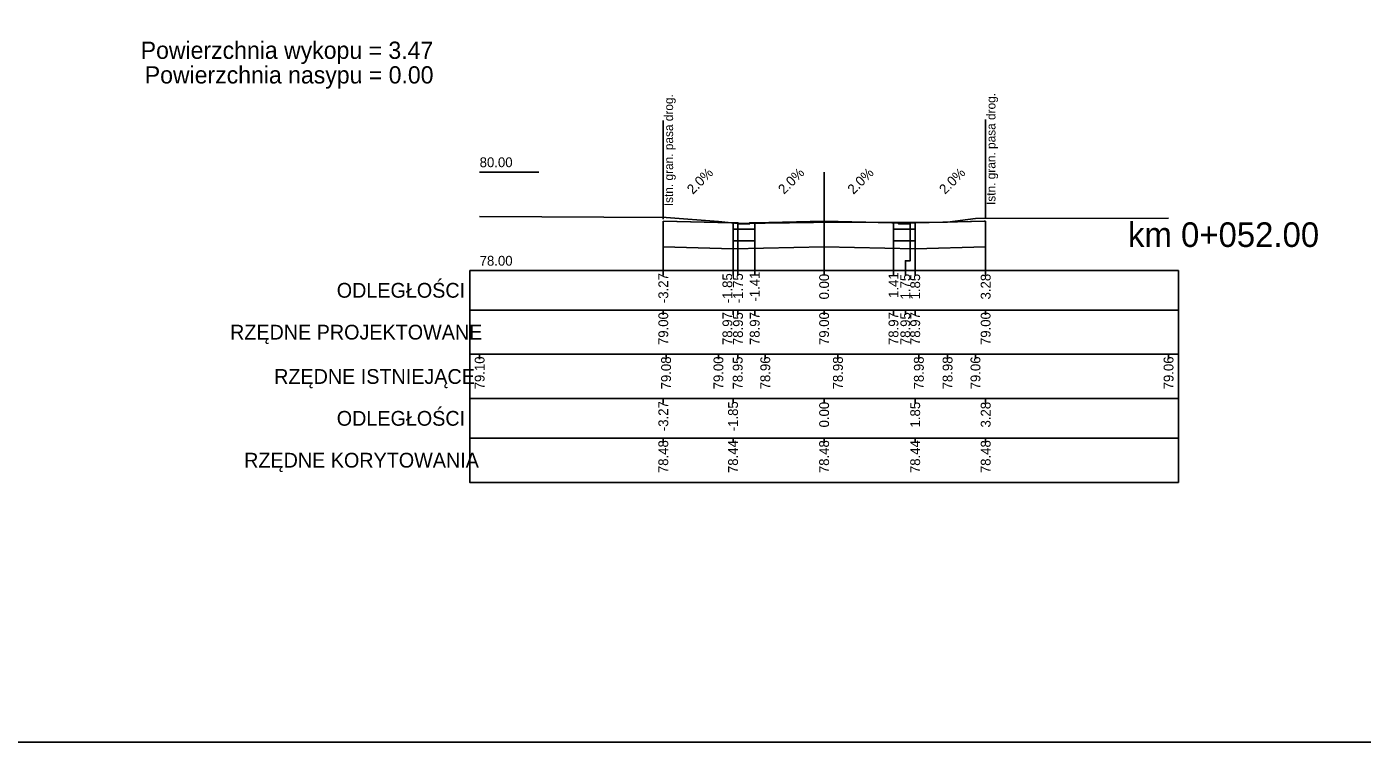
# Model space of a CAD drawing. Extents: x 7492871 to 7493499, y 5802964 to 5802992.
# Drawn here: x 7493132.5 to 7493159.64, y 5802963.88 to 5802978.41 of the extents above; entities that cross this region are included whole.
import ezdxf

# ---------------------------------------------------------------- set-up
doc = ezdxf.new("R2010")
doc.units = 0
for name, color, linetype in [('_wydruk', 7, 'Continuous'), ('d_pop_nasyp_opis', 7, 'Continuous'), ('d_pop_wykop_opis', 7, 'Continuous'), ('opisy_ramki_pop', 7, 'Continuous'), ('pop_comp_kostka', 7, 'Continuous'), ('pop_comp_lawa', 7, 'Continuous'), ('pop_comp_scieralna', 7, 'Continuous'), ('pop_granica_istn', 7, 'Continuous'), ('pop_opis', 7, 'Continuous'), ('pop_os', 7, 'Continuous'), ('pop_pikietaz', 7, 'Continuous'), ('pop_teren', 7, 'Continuous')]:
    doc.layers.add(name, color=color, linetype=linetype)

msp = doc.modelspace()

# ---------------------------------------------------------------- linework, layer by layer
msp.add_lwpolyline([(7493145.438, 5802974.46), (7493146.823, 5802974.432), (7493146.855, 5802974.432), (7493146.857, 5802974.432), (7493146.955, 5802974.432), (7493146.956, 5802974.412), (7493146.961, 5802974.412), (7493147.195, 5802974.412), (7493147.196, 5802974.432), (7493147.198, 5802974.432), (7493147.296, 5802974.432), (7493147.328, 5802974.432), (7493148.706, 5802974.46), (7493150.084, 5802974.432), (7493150.116, 5802974.432), (7493150.213, 5802974.432), (7493150.216, 5802974.432), (7493150.217, 5802974.412), (7493150.45, 5802974.412), (7493150.456, 5802974.412), (7493150.457, 5802974.432), (7493150.554, 5802974.432), (7493150.557, 5802974.432), (7493151.956, 5802974.46), (7493151.989, 5802974.46)])
at = {"layer": '_wydruk'}
msp.add_lwpolyline([(7492871.369, 5802992.281), (7493499.283, 5802992.281), (7493499.283, 5802963.881), (7492871.369, 5802963.881)], close=True, dxfattribs=at)
at = {"layer": 'opisy_ramki_pop'}
for points in [[(7493145.438, 5802973.94), (7493145.438, 5802973.659), (7493145.438, 5802973.659), (7493145.438, 5802973.459)], [(7493146.855, 5802973.903), (7493146.855, 5802973.659), (7493146.855, 5802973.659), (7493146.855, 5802973.459)], [(7493148.706, 5802973.94), (7493148.706, 5802973.659), (7493148.706, 5802973.659), (7493148.706, 5802973.459)], [(7493150.557, 5802973.903), (7493150.557, 5802973.659), (7493150.557, 5802973.659), (7493150.557, 5802973.459)], [(7493151.989, 5802973.94), (7493151.989, 5802973.659), (7493151.989, 5802973.659), (7493151.989, 5802973.459)]]:
    msp.add_lwpolyline(points, dxfattribs=at)
at = {"layer": 'pop_comp_kostka'}
for p, q in [((7493146.955, 5802974.432), (7493146.855, 5802974.432)), ((7493146.855, 5802974.432), (7493146.855, 5802974.302)), ((7493146.956, 5802974.412), (7493146.955, 5802974.432)), ((7493147.196, 5802974.432), (7493147.195, 5802974.412)), ((7493147.296, 5802974.432), (7493147.196, 5802974.432)), ((7493147.296, 5802974.302), (7493147.296, 5802974.432)), ((7493150.216, 5802974.432), (7493150.116, 5802974.432)), ((7493150.116, 5802974.432), (7493150.116, 5802974.302)), ((7493150.217, 5802974.412), (7493150.216, 5802974.432)), ((7493150.457, 5802974.432), (7493150.456, 5802974.412)), ((7493150.557, 5802974.432), (7493150.457, 5802974.432)), ((7493150.557, 5802974.302), (7493150.557, 5802974.432)), ((7493146.855, 5802974.302), (7493147.296, 5802974.302)), ((7493147.195, 5802974.412), (7493146.956, 5802974.412)), ((7493150.116, 5802974.302), (7493150.557, 5802974.302)), ((7493150.456, 5802974.412), (7493150.217, 5802974.412))]:
    msp.add_line(p, q, dxfattribs=at)
at = {"layer": 'pop_comp_lawa'}
for p, q in [((7493147.296, 5802974.302), (7493146.855, 5802974.302)), ((7493146.855, 5802974.302), (7493146.855, 5802974.062)), ((7493147.296, 5802974.062), (7493147.296, 5802974.302)), ((7493150.557, 5802974.302), (7493150.116, 5802974.302)), ((7493150.116, 5802974.302), (7493150.116, 5802974.062)), ((7493150.557, 5802974.062), (7493150.557, 5802974.302)), ((7493146.855, 5802974.062), (7493147.296, 5802974.062)), ((7493150.116, 5802974.062), (7493150.557, 5802974.062))]:
    msp.add_line(p, q, dxfattribs=at)
at = {"layer": 'pop_comp_scieralna'}
for p, q in [((7493146.855, 5802974.432), (7493145.438, 5802974.46)), ((7493145.438, 5802974.46), (7493145.438, 5802973.94)), ((7493146.855, 5802974.062), (7493146.855, 5802974.432)), ((7493148.706, 5802974.46), (7493147.296, 5802974.432)), ((7493147.296, 5802974.432), (7493147.296, 5802974.062)), ((7493148.706, 5802973.94), (7493148.706, 5802974.46)), ((7493150.116, 5802974.432), (7493148.706, 5802974.46)), ((7493148.706, 5802974.46), (7493148.706, 5802973.94)), ((7493150.116, 5802974.062), (7493150.116, 5802974.432)), ((7493151.989, 5802974.46), (7493150.557, 5802974.432)), ((7493150.557, 5802974.432), (7493150.557, 5802974.062)), ((7493151.989, 5802973.94), (7493151.989, 5802974.46)), ((7493145.438, 5802973.94), (7493146.855, 5802973.903)), ((7493147.296, 5802974.062), (7493146.855, 5802974.062)), ((7493146.855, 5802973.903), (7493148.706, 5802973.94)), ((7493148.706, 5802973.94), (7493150.557, 5802973.903)), ((7493150.557, 5802974.062), (7493150.116, 5802974.062)), ((7493150.557, 5802973.903), (7493151.989, 5802973.94))]:
    msp.add_line(p, q, dxfattribs=at)
at = {"layer": 'pop_granica_istn'}
for p, q in [((7493145.438, 5802975.006), (7493145.438, 5802976.506)), ((7493151.989, 5802975.031), (7493151.989, 5802976.531)), ((7493145.438, 5802974.506), (7493145.438, 5802975.006)), ((7493151.989, 5802974.531), (7493151.989, 5802975.031))]:
    msp.add_line(p, q, dxfattribs=at)
at = {"layer": 'pop_opis'}
for p, q in [((7493141.706, 5802975.459), (7493142.906, 5802975.459)), ((7493141.506, 5802973.459), (7493141.506, 5802971.759)), ((7493141.506, 5802973.459), (7493141.506, 5802971.759)), ((7493141.506, 5802973.459), (7493141.506, 5802971.759)), ((7493141.506, 5802973.459), (7493141.506, 5802971.759)), ((7493141.706, 5802973.459), (7493142.906, 5802973.459)), ((7493145.438, 5802973.359), (7493145.438, 5802973.459)), ((7493146.855, 5802973.359), (7493146.855, 5802973.459)), ((7493146.956, 5802973.359), (7493146.956, 5802973.459)), ((7493147.296, 5802973.359), (7493147.296, 5802973.459)), ((7493148.706, 5802973.359), (7493148.706, 5802973.459)), ((7493150.116, 5802973.359), (7493150.116, 5802973.459)), ((7493150.357, 5802973.359), (7493150.357, 5802973.459)), ((7493150.557, 5802973.359), (7493150.557, 5802973.459)), ((7493151.989, 5802973.359), (7493151.989, 5802973.459)), ((7493141.506, 5802972.659), (7493155.906, 5802972.659)), ((7493141.506, 5802972.659), (7493155.906, 5802972.659)), ((7493141.506, 5802972.659), (7493155.906, 5802972.659)), ((7493141.506, 5802972.659), (7493155.906, 5802972.659)), ((7493145.438, 5802972.559), (7493145.438, 5802972.659)), ((7493146.855, 5802972.559), (7493146.855, 5802972.659)), ((7493146.956, 5802972.559), (7493146.956, 5802972.659)), ((7493147.296, 5802972.559), (7493147.296, 5802972.659)), ((7493148.706, 5802972.559), (7493148.706, 5802972.659)), ((7493150.116, 5802972.559), (7493150.116, 5802972.659)), ((7493150.357, 5802972.559), (7493150.357, 5802972.659)), ((7493150.557, 5802972.559), (7493150.557, 5802972.659)), ((7493151.989, 5802972.559), (7493151.989, 5802972.659)), ((7493141.506, 5802971.759), (7493141.506, 5802970.859)), ((7493141.706, 5802971.659), (7493141.706, 5802971.759)), ((7493145.494, 5802971.659), (7493145.494, 5802971.759)), ((7493146.558, 5802971.659), (7493146.558, 5802971.759)), ((7493146.95, 5802971.659), (7493146.95, 5802971.759)), ((7493147.51, 5802971.659), (7493147.51, 5802971.759)), ((7493148.987, 5802971.659), (7493148.987, 5802971.759)), ((7493150.631, 5802971.659), (7493150.631, 5802971.759)), ((7493151.215, 5802971.659), (7493151.215, 5802971.759)), ((7493151.782, 5802971.659), (7493151.782, 5802971.759)), ((7493155.706, 5802971.659), (7493155.706, 5802971.759)), ((7493141.506, 5802970.859), (7493141.506, 5802969.159)), ((7493145.438, 5802970.759), (7493145.438, 5802970.859)), ((7493146.855, 5802970.759), (7493146.855, 5802970.859)), ((7493148.706, 5802970.759), (7493148.706, 5802970.859)), ((7493150.557, 5802970.759), (7493150.557, 5802970.859)), ((7493151.989, 5802970.759), (7493151.989, 5802970.859)), ((7493141.506, 5802970.059), (7493155.906, 5802970.059)), ((7493145.438, 5802969.959), (7493145.438, 5802970.059)), ((7493146.855, 5802969.959), (7493146.855, 5802970.059)), ((7493148.706, 5802969.959), (7493148.706, 5802970.059)), ((7493150.557, 5802969.959), (7493150.557, 5802970.059)), ((7493151.989, 5802969.959), (7493151.989, 5802970.059))]:
    msp.add_line(p, q, dxfattribs=at)
for points in [[(7493145.438, 5802974.46), (7493145.438, 5802973.659), (7493145.438, 5802973.659), (7493145.438, 5802973.459)], [(7493146.855, 5802974.432), (7493146.855, 5802973.659), (7493146.855, 5802973.659), (7493146.855, 5802973.459)], [(7493147.296, 5802974.432), (7493147.296, 5802973.659), (7493147.296, 5802973.659), (7493147.296, 5802973.459)], [(7493148.706, 5802974.46), (7493148.706, 5802973.659), (7493148.706, 5802973.659), (7493148.706, 5802973.459)], [(7493150.116, 5802974.432), (7493150.116, 5802973.659), (7493150.116, 5802973.659), (7493150.116, 5802973.459)], [(7493150.557, 5802974.432), (7493150.557, 5802973.659), (7493150.557, 5802973.659), (7493150.557, 5802973.459)], [(7493151.989, 5802974.46), (7493151.989, 5802973.659), (7493151.989, 5802973.659), (7493151.989, 5802973.459)], [(7493146.956, 5802974.412), (7493146.956, 5802973.659), (7493146.956, 5802973.659), (7493146.956, 5802973.459)], [(7493150.456, 5802974.412), (7493150.456, 5802973.659), (7493150.357, 5802973.659), (7493150.357, 5802973.459)]]:
    msp.add_lwpolyline(points, dxfattribs=at)
for points in [[(7493141.506, 5802973.459), (7493141.506, 5802971.759), (7493155.906, 5802971.759), (7493155.906, 5802973.459)], [(7493141.506, 5802973.459), (7493141.506, 5802971.759), (7493155.906, 5802971.759), (7493155.906, 5802973.459)], [(7493141.506, 5802973.459), (7493141.506, 5802971.759), (7493155.906, 5802971.759), (7493155.906, 5802973.459)], [(7493141.506, 5802973.459), (7493141.506, 5802971.759), (7493155.906, 5802971.759), (7493155.906, 5802973.459)], [(7493141.506, 5802971.759), (7493141.506, 5802970.859), (7493155.906, 5802970.859), (7493155.906, 5802971.759)], [(7493141.506, 5802970.859), (7493141.506, 5802969.159), (7493155.906, 5802969.159), (7493155.906, 5802970.859)]]:
    msp.add_lwpolyline(points, close=True, dxfattribs=at)
at = {"layer": 'pop_os'}
msp.add_line((7493148.706, 5802975.459), (7493148.706, 5802973.459), dxfattribs=at)
at = {"layer": 'pop_teren'}
msp.add_lwpolyline([(7493141.706, 5802974.561), (7493145.494, 5802974.538), (7493146.558, 5802974.459), (7493146.95, 5802974.413), (7493147.51, 5802974.42), (7493148.987, 5802974.44), (7493150.631, 5802974.438), (7493151.215, 5802974.441), (7493151.782, 5802974.515), (7493155.706, 5802974.523)], dxfattribs=at)

# ---------------------------------------------------------------- texts
at = {"layer": 'd_pop_nasyp_opis'}
msp.add_text('Powierzchnia nasypu = 0.00', height=0.35, dxfattribs=at).set_placement((7493134.901, 5802977.259))
at = {"layer": 'd_pop_wykop_opis'}
msp.add_text('Powierzchnia wykopu = 3.47', height=0.35, dxfattribs=at).set_placement((7493134.818, 5802977.759))
at = {"layer": 'pop_granica_istn'}
for p in [(7493145.637, 5802974.767), (7493152.188, 5802974.792)]:
    msp.add_text('Istn. gran. pasa drog.', height=0.18, rotation=90, dxfattribs=at).set_placement(p)
at = {"layer": 'pop_opis'}
for s, height, p in [('80.00', 0.2, (7493141.706, 5802975.559)), ('78.00', 0.2, (7493141.706, 5802973.559)), ('ODLEGŁOŚCI', 0.3, (7493138.802, 5802972.909)), ('ODLEGŁOŚCI', 0.3, (7493138.802, 5802972.909)), ('ODLEGŁOŚCI', 0.3, (7493138.802, 5802972.909)), ('ODLEGŁOŚCI', 0.3, (7493138.802, 5802972.909)), ('RZĘDNE PROJEKTOWANE', 0.3, (7493136.634, 5802972.059)), ('RZĘDNE PROJEKTOWANE', 0.3, (7493136.634, 5802972.059)), ('RZĘDNE PROJEKTOWANE', 0.3, (7493136.634, 5802972.059)), ('RZĘDNE PROJEKTOWANE', 0.3, (7493136.634, 5802972.059)), ('RZĘDNE ISTNIEJĄCE', 0.3, (7493137.53, 5802971.159)), ('ODLEGŁOŚCI', 0.3, (7493138.802, 5802970.309)), ('RZĘDNE KORYTOWANIA', 0.3, (7493136.92, 5802969.459))]:
    msp.add_text(s, height=height, dxfattribs=at).set_placement(p)
for s, rotation, p in [('2.0%', 45, (7493146.038, 5802974.996)), ('2.0%', 45, (7493147.892, 5802974.996)), ('2.0%', 45, (7493149.302, 5802974.996)), ('2.0%', 45, (7493151.164, 5802974.996)), ('-3.27', 90, (7493145.538, 5802972.798)), ('-1.85', 90, (7493146.841, 5802972.796)), ('-1.75', 90, (7493147.056, 5802972.796)), ('-1.41', 90, (7493147.396, 5802972.829)), ('0.00', 90, (7493148.806, 5802972.874)), ('1.41', 90, (7493150.216, 5802972.905)), ('1.75', 90, (7493150.457, 5802972.873)), ('1.85', 90, (7493150.657, 5802972.873)), ('3.28', 90, (7493152.089, 5802972.873)), ('79.00', 90, (7493145.538, 5802971.947)), ('78.97', 90, (7493146.841, 5802971.947)), ('78.95', 90, (7493147.056, 5802971.945)), ('78.97', 90, (7493147.396, 5802971.947)), ('79.00', 90, (7493148.806, 5802971.947)), ('78.97', 90, (7493150.216, 5802971.947)), ('78.95', 90, (7493150.457, 5802971.945)), ('78.97', 90, (7493150.657, 5802971.947)), ('79.00', 90, (7493152.089, 5802971.947)), ('79.10', 90, (7493141.806, 5802971.047)), ('79.08', 90, (7493145.594, 5802971.046)), ('79.00', 90, (7493146.658, 5802971.047)), ('78.95', 90, (7493147.05, 5802971.045)), ('78.96', 90, (7493147.61, 5802971.047)), ('78.98', 90, (7493149.087, 5802971.046)), ('78.98', 90, (7493150.731, 5802971.046)), ('78.98', 90, (7493151.315, 5802971.046)), ('79.06', 90, (7493151.882, 5802971.047)), ('79.06', 90, (7493155.806, 5802971.047)), ('-3.27', 90, (7493145.538, 5802970.198)), ('-1.85', 90, (7493146.955, 5802970.196)), ('0.00', 90, (7493148.806, 5802970.274)), ('1.85', 90, (7493150.657, 5802970.273)), ('3.28', 90, (7493152.089, 5802970.273)), ('78.48', 90, (7493145.538, 5802969.346)), ('78.44', 90, (7493146.955, 5802969.347)), ('78.48', 90, (7493148.806, 5802969.346)), ('78.44', 90, (7493150.657, 5802969.347)), ('78.48', 90, (7493152.089, 5802969.346))]:
    msp.add_text(s, height=0.2, rotation=rotation, dxfattribs=at).set_placement(p)
at = {"layer": 'pop_pikietaz'}
msp.add_text('km 0+052.00', height=0.5, dxfattribs=at).set_placement((7493154.882, 5802973.939))

doc.saveas('drawing.dxf')
